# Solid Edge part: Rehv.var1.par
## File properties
Author: jaanm
Template: Ansi Metric part.par
Last saved by: jaanm
Revision: 9
Application: Solid Edge
Accuracy: 0,990
Face Style: Model Default
Coef. of Thermal Exp: 0.0
Thermal Conductivity: 0.0
Specific Heat: 0.0
Modulus of Elasticity: 0.0
Poisson's Ratio: 0.0
Yield Stress: 0.0
Ultimate Stress: 0.0
Elongation: 0.0
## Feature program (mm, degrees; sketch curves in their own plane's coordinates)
sketch for "unnamed RevolvedProtrusion 1" plane through (0, 0, 0) normal (1, 0, 0) x-axis (0, 1, 0)
  arc centre (-50, 125) radius 50 from (-100, 125) to (-50, 175) cw
  line (0, 175) -> (-50, 175)
  line (0, 175) -> (50, 175)
  arc centre (50, 125) radius 50 from (100, 125) to (50, 175) ccw
  arc centre (100, 99.375) radius 25.625 from (100, 125) to (75, 105) ccw
  line (75, 105) -> (65, 105)
  arc centre (90, 105) radius 25 from (65, 105) to (75, 125) cw
  arc centre (50, 125) radius 25 from (50, 150) to (75, 125) cw
  line (0, 150) -> (50, 150)
  line (-50, 150) -> (0, 150)
  arc centre (-50, 125) radius 25 from (-75, 125) to (-50, 150) cw
  arc centre (-90, 105) radius 25 from (-65, 105) to (-75, 125) ccw
  line (-75, 105) -> (-65, 105)
  arc centre (-100, 99.375) radius 25.625 from (-100, 125) to (-75, 105) cw
revolve "unnamed RevolvedProtrusion 1" add finite 360 deg
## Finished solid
Body 1: solid body, 12 faces, 12 edges, 0 vertices.
  Faces by surface: torus 8, cylinder 4
  Edges by curve: circle 12
Bounding box of the edges (mm; curved faces can reach further): 350.000 x 200.000 x 350.000, from (-175, -100, -175) to (175, 100, 175).
Cylindrical faces by radius (mm): R105 x2, R150 x1, R175 x1
Toroidal faces (ring radius, tube radius in mm): R99.375 r25.625 x2, R105 r25 x2, R125 r25 x2, R125 r50 x2
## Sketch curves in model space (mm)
circle centre (1.6946, 100, 0) radius 103.634
line (0, 0, 0) -> (0, 117.9101, 0)
arc centre (0, 50, 125) radius 50 from (0, 100, 125) through (0, 84.3121, 161.3687) to (0, 50, 175)
arc centre (0, 100, 99.375) radius 25.625 from (0, 100, 125) through (0, 83.4121, 118.9066) to (0, 75, 105)
line (0, 75, 105) -> (0, 65, 105)
arc centre (0, 90, 105) radius 25 from (0, 65, 105) through (0, 67.6393, 116.1803) to (0, 75, 125)
arc centre (0, 50, 125) radius 25 from (0, 50, 150) through (0, 68.1843, 142.156) to (0, 75, 125)
line (0, 0, 150) -> (0, 50, 150)
line (0, -50, 150) -> (0, 0, 150)
arc centre (0, -50, 125) radius 25 from (0, -75, 125) through (0, -67.156, 143.1843) to (0, -50, 150)
arc centre (0, -90, 105) radius 25 from (0, -65, 105) through (0, -67.6393, 116.1803) to (0, -75, 125)
line (0, -75, 105) -> (0, -65, 105)
arc centre (0, -100, 99.375) radius 25.625 from (0, -100, 125) through (0, -83.4121, 118.9066) to (0, -75, 105)
arc centre (0, -50, 125) radius 50 from (0, -100, 125) through (0, -84.3121, 161.3687) to (0, -50, 175)
line (0, 0, 175) -> (0, -50, 175)
line (0, 0, 175) -> (0, 50, 175)
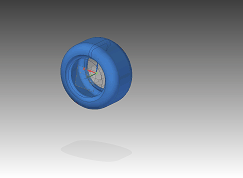
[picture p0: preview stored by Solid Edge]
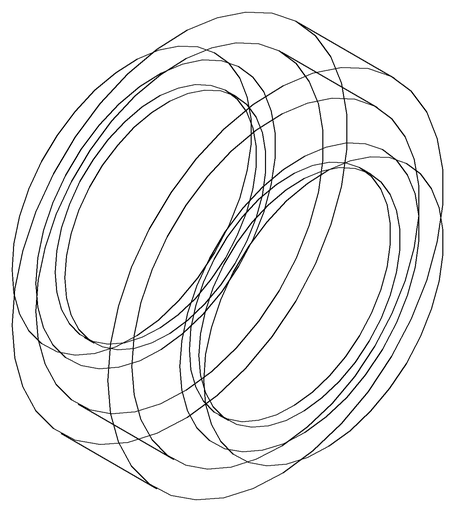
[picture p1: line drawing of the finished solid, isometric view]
